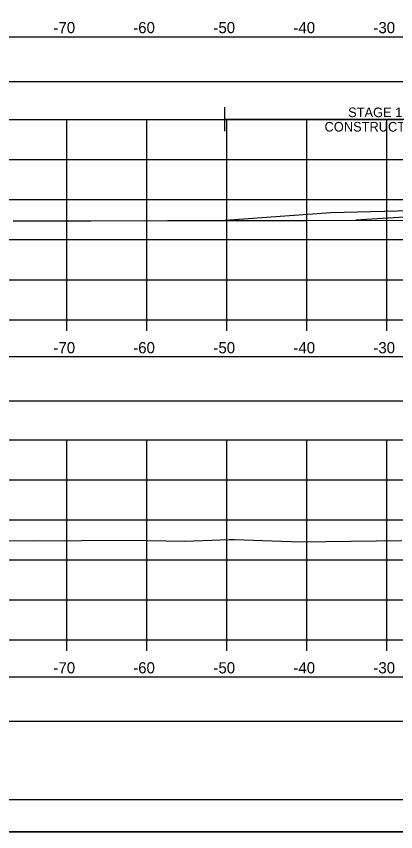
# Model space of a CAD drawing. Extents: x 1369627 to 1374022, y 380035 to 398173.
# Drawn here: x 1372022.2 to 1372069.7, y 381958.8 to 382060.7 of the extents above; entities that cross this region are included whole.
import ezdxf

# ---------------------------------------------------------------- set-up
doc = ezdxf.new("R2010")
doc.units = 0
for name, color, linetype in [('Default', 7, 'Continuous'), ('R_Axis', 7, 'Continuous'), ('R_Axis Annot', 7, 'Continuous'), ('R_Border', 7, 'Continuous'), ('R_Drive', 7, 'Continuous'), ('R_Exist Surface', 7, 'Continuous'), ('R_Grid', 7, 'Continuous'), ('R_MOT', 7, 'Continuous'), ('R_No Plot', 7, 'Continuous'), ('T_Vehicle Path Lt Minor', 7, 'Continuous')]:
    doc.layers.add(name, color=color, linetype=linetype)

msp = doc.modelspace()

# ---------------------------------------------------------------- linework, layer by layer
at = {"layer": 'Default'}
for points in [[(1371948.53, 382052.57), (1372248.53, 382052.57), (1372248.53, 382058.09), (1371948.53, 382058.09)], [(1371948.53, 382012.65), (1372248.53, 382012.65), (1372248.53, 382018.17), (1371948.53, 382018.17)], [(1371948.53, 381972.61), (1372248.53, 381972.61), (1372248.53, 381978.13), (1371948.53, 381978.13)]]:
    msp.add_lwpolyline(points, close=True, dxfattribs=at)
at = {"layer": 'R_Axis'}
for p, q in [((1371948.53, 382022.8), (1372248.53, 382022.8)), ((1372028.53, 382021.4), (1372028.53, 382022.8)), ((1372038.53, 382021.4), (1372038.53, 382022.8)), ((1372048.53, 382021.4), (1372048.53, 382022.8)), ((1372058.53, 382021.4), (1372058.53, 382022.8)), ((1372068.53, 382021.4), (1372068.53, 382022.8)), ((1371948.53, 381982.8), (1372248.53, 381982.8)), ((1372028.53, 381981.4), (1372028.53, 381982.8)), ((1372038.53, 381981.4), (1372038.53, 381982.8)), ((1372048.53, 381981.4), (1372048.53, 381982.8)), ((1372058.53, 381981.4), (1372058.53, 381982.8)), ((1372068.53, 381981.4), (1372068.53, 381982.8))]:
    msp.add_line(p, q, dxfattribs=at)
at = {"layer": 'R_Border'}
msp.add_line((1372256.71, 381962.8), (1371940.53, 381962.8), dxfattribs=at)
at = {"layer": 'R_Drive'}
msp.add_lwpolyline([(1372071.53, 382036.41), (1372061.53, 382036.15), (1372048.33, 382035.2)], dxfattribs=at)
at = {"layer": 'R_Exist Surface'}
for points in [[(1372021.83, 382035.17), (1372029.83, 382035.17), (1372031.52, 382035.16), (1372041.11, 382035.19), (1372041.92, 382035.2), (1372049.52, 382035.2), (1372058.53, 382035.2), (1372062.16, 382035.22), (1372074.73, 382035.21)], [(1372016.44, 381995.21), (1372024.41, 381995.18), (1372036.38, 381995.24), (1372043.24, 381995.14), (1372048.88, 381995.33), (1372049.49, 381995.34), (1372057.77, 381995.06), (1372070.44, 381995.2)]]:
    msp.add_lwpolyline(points, dxfattribs=at)
at = {"layer": 'R_Grid'}
for p, q in [((1371948.53, 382047.8), (1372248.53, 382047.8)), ((1372028.53, 382022.8), (1372028.53, 382047.8)), ((1372038.53, 382022.8), (1372038.53, 382047.8)), ((1372048.53, 382022.8), (1372048.53, 382047.8)), ((1372058.53, 382022.8), (1372058.53, 382047.8)), ((1372068.53, 382022.8), (1372068.53, 382047.8)), ((1371948.53, 382042.8), (1372248.53, 382042.8)), ((1371948.53, 382037.8), (1372248.53, 382037.8)), ((1371948.53, 382032.8), (1372248.53, 382032.8)), ((1371948.53, 382027.8), (1372248.53, 382027.8)), ((1371948.53, 382022.8), (1372248.53, 382022.8)), ((1371948.53, 382007.8), (1372248.53, 382007.8)), ((1372028.53, 381982.8), (1372028.53, 382007.8)), ((1372038.53, 381982.8), (1372038.53, 382007.8)), ((1372048.53, 381982.8), (1372048.53, 382007.8)), ((1372058.53, 381982.8), (1372058.53, 382007.8)), ((1372068.53, 381982.8), (1372068.53, 382007.8)), ((1371948.53, 382002.8), (1372248.53, 382002.8)), ((1371948.53, 381997.8), (1372248.53, 381997.8)), ((1371948.53, 381992.8), (1372248.53, 381992.8)), ((1371948.53, 381987.8), (1372248.53, 381987.8)), ((1371948.53, 381982.8), (1372248.53, 381982.8))]:
    msp.add_line(p, q, dxfattribs=at)
at = {"layer": 'R_MOT'}
for p, q in [((1372048.29, 382046.35), (1372048.29, 382049.35)), ((1372048.29, 382047.85), (1372126.64, 382047.85))]:
    msp.add_line(p, q, dxfattribs=at)
at = {"layer": 'R_No Plot'}
for p, q in [((1372073.53, 382035.8), (1372064.67, 382035.22)), ((1371928.13, 381958.82), (1372261.46, 381958.82))]:
    msp.add_line(p, q, dxfattribs=at)
for points in [[(1371928.12, 382172.16), (1372261.46, 382172.16), (1372261.46, 381958.82), (1371928.12, 381958.82)], [(1372174.45, 382168.26), (1372194.07, 382168.26), (1372194.07, 382158.38), (1372210.18, 382158.38), (1372233.38, 382158.38), (1372233.38, 382125.71), (1372256.59, 382125.71), (1372256.71, 381962.8), (1371940.53, 381962.8), (1371940.53, 382168.26)]]:
    msp.add_lwpolyline(points, close=True, dxfattribs=at)
at = {"layer": 'T_Vehicle Path Lt Minor'}
for points in [[(1372071.53, 382036.41), (1372061.53, 382036.15), (1372048.33, 382035.2)], [(1372048.33, 382035.2), (1372049.52, 382035.2), (1372058.53, 382035.2), (1372062.16, 382035.22), (1372070.67, 382035.21)]]:
    msp.add_lwpolyline(points, dxfattribs=at)

# ---------------------------------------------------------------- texts
at = {"layer": 'R_Axis Annot'}
for s, p in [('-70', (1372026.87, 382058.6)), ('-60', (1372036.84, 382058.6)), ('-50', (1372046.87, 382058.6)), ('-40', (1372056.87, 382058.6)), ('-30', (1372066.87, 382058.6)), ('-70', (1372026.87, 382018.6)), ('-60', (1372036.84, 382018.6)), ('-50', (1372046.87, 382018.6)), ('-40', (1372056.87, 382018.6)), ('-30', (1372066.87, 382018.6)), ('-70', (1372026.87, 381978.6)), ('-60', (1372036.84, 381978.6)), ('-50', (1372046.87, 381978.6)), ('-40', (1372056.87, 381978.6)), ('-30', (1372066.87, 381978.6))]:
    msp.add_text(s, height=1.4, dxfattribs=at).set_placement(p)
at = {"layer": 'R_MOT'}
for s, p in [('STAGE 1', (1372063.71, 382048.11)), ('CONSTRUCTION', (1372060.76, 382046.31))]:
    msp.add_text(s, height=1.2, dxfattribs=at).set_placement(p)

doc.saveas('drawing.dxf')
